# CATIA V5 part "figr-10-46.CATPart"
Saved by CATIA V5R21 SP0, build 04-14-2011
Part number: Part1
Bounding box of the stored display mesh (mm): x -80.563 to 63.541, y -72 to 69, z -55 to 6.847
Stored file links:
  D:\CATIA V5R21 E-RESOURCES\CATIA-V5R21\catia-v5r21-prt\c10-catia-v5r20-prt\c10-catia-v5r21-figr-10-46.CATPart
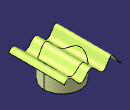
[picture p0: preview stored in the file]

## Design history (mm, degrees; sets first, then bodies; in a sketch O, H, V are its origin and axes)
Set1
  Sketch1 on xy-plane, origin (0, 0, 0), H (-1, 0, 0), V (0, -1, 0)
    circle A1 centre (0, 0) radius 45.985
  Extrude1: Element1 Sketch1, Lim1 56, Lim2 55, Direction xy-plane
  Sketch2 on zx-plane, origin (0, 0, 0), H (1, 0, 0), V (0, 0, -1)
    spline S1 through (-80.5635, 24.8913) (-73.6025, 19.8803) (-54.8525, -3.3629) (-35.1982, 19.8803) (-2.6271, -1.6506) (16.6996, 17.2854) (52.4104, -6.7877) (63.5409, 1.5862)
  Extrude2: Element1 Sketch2, Lim1 72, Lim2 69, Direction Sketch1.V
  Split1: ToCut Extrude1, Cutting Extrude2
Body1 (main body)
